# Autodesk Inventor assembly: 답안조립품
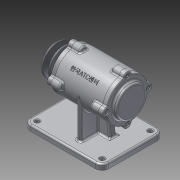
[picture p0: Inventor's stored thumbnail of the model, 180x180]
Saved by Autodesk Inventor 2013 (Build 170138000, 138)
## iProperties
Created: 2015-12
Part Number: 답안조립품
Document SubType Name: Assembly
Designer: default
Author: default
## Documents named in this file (11)
- C:\Documents and Settings\default\바탕 화면\451208V1007\답안조립품.iam
- C:\Documents and Settings\default\바탕 화면\451208V1007\1-본체.ipt
- C:\Documents and Settings\default\바탕 화면\451208V1007\베어링 6204.ipt
- C:\Documents and Settings\default\바탕 화면\451208V1007\커버.ipt
- C:\Documents and Settings\default\바탕 화면\451208V1007\커버2.ipt
- C:\Documents and Settings\default\바탕 화면\451208V1007\축.ipt
- C:\Documents and Settings\default\바탕 화면\451208V1007\볼트 M4 x 12.ipt
- C:\Documents and Settings\default\바탕 화면\451208V1007\오일실.ipt
- C:\Documents and Settings\default\바탕 화면\451208V1007\키(4 x 4 x 12).ipt
- C:\Documents and Settings\default\바탕 화면\451208V1007\V-벨트풀리.ipt
- C:\Documents and Settings\default\바탕 화면\451208V1007\너트 M12x1.25.ipt
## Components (7 placed, 6 different names)
1. 1-본체:1
2. KS B 2023 6204 - 20 x 47 x 14:1
3. KS B 2023 6204 - 20 x 47 x 14:2
4. KS B 2804 D D - 20 32 8:1
5. KS B 1311 (I) 4 x 4 x 12:1 — 각도:1, 각도:2
6. V-벨트풀리:1 — 각도:2
7. KS B 1012 클래스 1 일반 - 미터 M12x1.25:1
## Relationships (2: Angle 2)
- 각도:1 [Angle]: KS B 1311 (I) 4 x 4 x 12:1
- 각도:2 [Angle]: KS B 1311 (I) 4 x 4 x 12:1 ↔ V-벨트풀리:1
